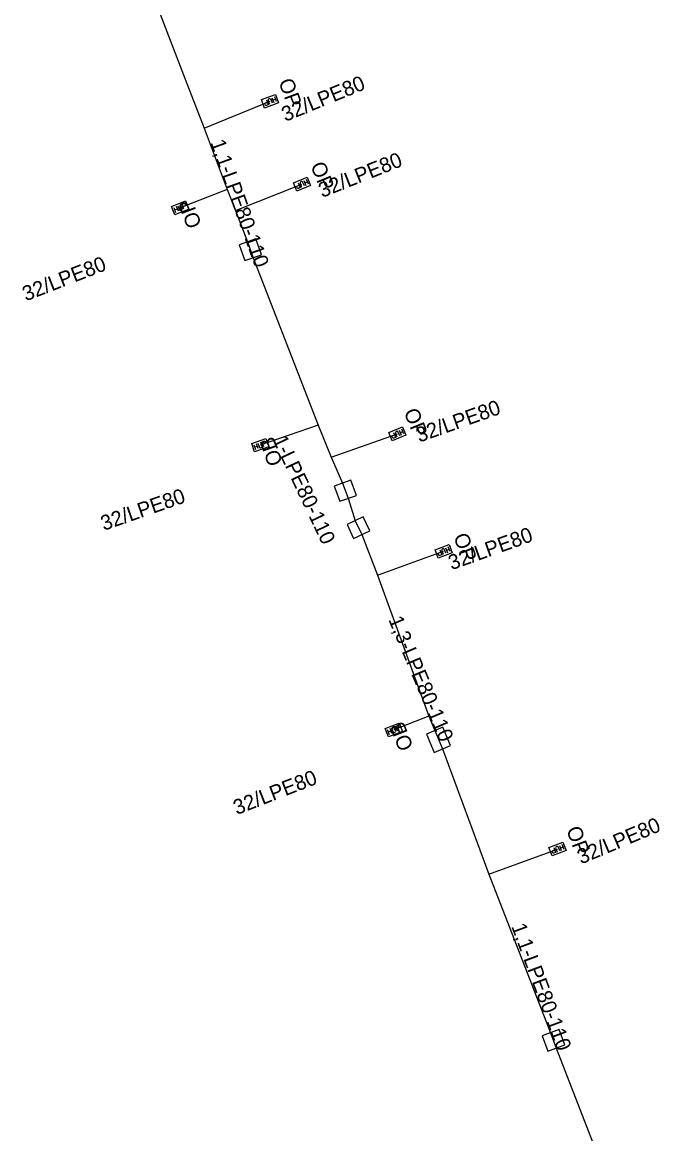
# Model space of a CAD drawing. Extents: x -762509 to -761250, y -1153000 to -1152256.
# Drawn here: x -761501.9 to -761459.2, y -1152484.2 to -1152409.7 of the extents above; entities that cross this region are included whole.
import ezdxf

# ---------------------------------------------------------------- set-up
doc = ezdxf.new("R2010")
doc.units = 0
for name, color, linetype in [('Vrstva 21', 7, 'Continuous'), ('Vrstva 29', 7, 'Continuous'), ('Vrstva 31', 7, 'Continuous'), ('Vrstva 32', 7, 'Continuous')]:
    doc.layers.add(name, color=color, linetype=linetype)

msp = doc.modelspace()

# ---------------------------------------------------------------- linework, layer by layer
at = {"layer": 'Vrstva 21'}
msp.add_lwpolyline([(-761494.58, -1152404.14), (-761490.85, -1152413.85), (-761489.7, -1152416.84), (-761488.16, -1152420.95), (-761487.6, -1152422.35), (-761486.8, -1152424.45), (-761486.42, -1152425.51), (-761482.06, -1152436.72), (-761481.18, -1152438.87), (-761480.42, -1152440.61), (-761480.05, -1152441.63), (-761479.58, -1152443.13), (-761479.14, -1152444.06), (-761478.09, -1152446.77), (-761474.65, -1152456.23), (-761474.25, -1152457.19), (-761473.73, -1152458.42), (-761470.62, -1152466.8), (-761466.48, -1152477.43), (-761466.1, -1152478.45), (-761462.35, -1152488.13)], dxfattribs=at)
at = {"layer": 'Vrstva 29'}
for points in [[(-761487.36, -1152424.65), (-761486.98, -1152425.71), (-761485.86, -1152425.31), (-761486.24, -1152424.25)], [(-761480.98, -1152440.81), (-761480.61, -1152441.83), (-761479.49, -1152441.43), (-761479.86, -1152440.41)], [(-761480.12, -1152443.39), (-761479.68, -1152444.32), (-761478.6, -1152443.8), (-761479.04, -1152442.87)], [(-761474.8, -1152457.42), (-761474.28, -1152458.65), (-761473.18, -1152458.19), (-761473.7, -1152456.96)], [(-761467.04, -1152477.64), (-761466.66, -1152478.66), (-761465.54, -1152478.24), (-761465.92, -1152477.22)]]:
    msp.add_lwpolyline(points, close=True, dxfattribs=at)
at = {"layer": 'Vrstva 31'}
for points in [[(-761489.7, -1152416.84), (-761489.69, -1152416.83), (-761485.28, -1152415.03)], [(-761488.16, -1152420.95), (-761491.3, -1152422.17)], [(-761487.6, -1152422.35), (-761483.14, -1152420.58)], [(-761482.06, -1152436.72), (-761485.94, -1152438.07)], [(-761481.18, -1152438.87), (-761476.75, -1152437.31)], [(-761478.09, -1152446.77), (-761473.65, -1152445.18)], [(-761474.65, -1152456.23), (-761476.99, -1152457.14)], [(-761470.62, -1152466.8), (-761466.02, -1152465.12)]]:
    msp.add_lwpolyline(points, dxfattribs=at)
at = {"layer": 'Vrstva 32'}
for p, q in [((-761485.529, -1152414.937), (-761485.406, -1152415.264)), ((-761485.155, -1152414.797), (-761485.032, -1152415.124)), ((-761484.902, -1152414.899), (-761485.09, -1152414.97)), ((-761484.844, -1152415.054), (-761484.967, -1152414.726)), ((-761483.022, -1152420.343), (-761482.89, -1152420.667)), ((-761482.704, -1152420.591), (-761482.836, -1152420.267)), ((-761483.392, -1152420.493), (-761483.26, -1152420.817)), ((-761482.766, -1152420.438), (-761482.952, -1152420.514)), ((-761491.736, -1152422.152), (-761491.609, -1152422.478)), ((-761491.676, -1152422.306), (-761491.489, -1152422.233)), ((-761491.422, -1152422.405), (-761491.549, -1152422.079)), ((-761491.05, -1152422.261), (-761491.177, -1152421.935)), ((-761477.002, -1152437.224), (-761476.869, -1152437.548)), ((-761476.633, -1152437.073), (-761476.5, -1152437.397)), ((-761476.376, -1152437.168), (-761476.562, -1152437.244)), ((-761476.314, -1152437.32), (-761476.447, -1152436.996)), ((-761486.375, -1152438.036), (-761486.26, -1152438.367)), ((-761486.321, -1152438.192), (-761486.131, -1152438.126)), ((-761486.07, -1152438.301), (-761486.185, -1152437.97)), ((-761485.694, -1152438.17), (-761485.809, -1152437.839)), ((-761473.214, -1152445.201), (-761473.339, -1152444.874)), ((-761473.9, -1152445.087), (-761473.775, -1152445.415)), ((-761473.527, -1152444.946), (-761473.402, -1152445.273)), ((-761473.273, -1152445.047), (-761473.461, -1152445.119)), ((-761477.426, -1152457.122), (-761477.299, -1152457.448)), ((-761477.366, -1152457.276), (-761477.179, -1152457.203)), ((-761477.112, -1152457.375), (-761477.239, -1152457.049)), ((-761476.74, -1152457.231), (-761476.867, -1152456.905)), ((-761466.269, -1152465.027), (-761466.146, -1152465.354)), ((-761465.895, -1152464.887), (-761465.773, -1152465.214)), ((-761465.642, -1152464.989), (-761465.83, -1152465.06)), ((-761465.584, -1152465.144), (-761465.707, -1152464.816))]:
    msp.add_line(p, q, dxfattribs=at)
for points in [[(-761484.707, -1152415.136), (-761485.643, -1152415.487), (-761485.854, -1152414.925), (-761484.917, -1152414.574), (-761484.707, -1152415.136)], [(-761485.406, -1152415.264), (-761485.528, -1152415.31), (-761485.573, -1152415.309), (-761485.593, -1152415.299), (-761485.617, -1152415.273), (-761485.635, -1152415.226), (-761485.633, -1152415.19), (-761485.625, -1152415.17), (-761485.592, -1152415.14), (-761485.47, -1152415.094)], [(-761485.125, -1152415.159), (-761485.213, -1152414.924), (-761485.244, -1152414.883), (-761485.284, -1152414.863), (-761485.329, -1152414.862), (-761485.357, -1152414.872), (-761485.39, -1152414.903), (-761485.405, -1152414.944), (-761485.401, -1152414.995), (-761485.313, -1152415.23)], [(-761482.564, -1152420.669), (-761483.49, -1152421.046), (-761483.717, -1152420.491), (-761482.791, -1152420.113), (-761482.564, -1152420.669)], [(-761483.26, -1152420.817), (-761483.38, -1152420.866), (-761483.425, -1152420.867), (-761483.445, -1152420.857), (-761483.471, -1152420.832), (-761483.49, -1152420.786), (-761483.489, -1152420.75), (-761483.481, -1152420.73), (-761483.449, -1152420.698), (-761483.328, -1152420.649)], [(-761482.982, -1152420.704), (-761483.077, -1152420.472), (-761483.108, -1152420.432), (-761483.149, -1152420.413), (-761483.195, -1152420.413), (-761483.221, -1152420.424), (-761483.254, -1152420.455), (-761483.268, -1152420.497), (-761483.263, -1152420.548), (-761483.168, -1152420.78)], [(-761491.875, -1152422.072), (-761490.942, -1152421.709), (-761490.725, -1152422.269), (-761491.657, -1152422.631), (-761491.875, -1152422.072)], [(-761491.456, -1152422.043), (-761491.366, -1152422.277), (-761491.335, -1152422.318), (-761491.294, -1152422.337), (-761491.249, -1152422.338), (-761491.222, -1152422.327), (-761491.189, -1152422.296), (-761491.173, -1152422.255), (-761491.178, -1152422.204), (-761491.269, -1152421.97)], [(-761491.177, -1152421.935), (-761491.056, -1152421.888), (-761491.01, -1152421.888), (-761490.991, -1152421.898), (-761490.966, -1152421.923), (-761490.947, -1152421.97), (-761490.949, -1152422.006), (-761490.957, -1152422.026), (-761490.99, -1152422.057), (-761491.111, -1152422.104)], [(-761476.174, -1152437.398), (-761477.099, -1152437.777), (-761477.327, -1152437.222), (-761476.402, -1152436.843), (-761476.174, -1152437.398)], [(-761476.869, -1152437.548), (-761476.989, -1152437.597), (-761477.035, -1152437.597), (-761477.055, -1152437.588), (-761477.08, -1152437.563), (-761477.099, -1152437.517), (-761477.099, -1152437.481), (-761477.091, -1152437.46), (-761477.058, -1152437.429), (-761476.938, -1152437.379)], [(-761476.591, -1152437.434), (-761476.687, -1152437.202), (-761476.718, -1152437.162), (-761476.759, -1152437.143), (-761476.805, -1152437.143), (-761476.832, -1152437.154), (-761476.864, -1152437.186), (-761476.878, -1152437.227), (-761476.873, -1152437.278), (-761476.777, -1152437.51)], [(-761486.511, -1152437.951), (-761485.566, -1152437.622), (-761485.369, -1152438.189), (-761486.314, -1152438.518), (-761486.511, -1152437.951)], [(-761486.092, -1152437.938), (-761486.009, -1152438.175), (-761485.98, -1152438.216), (-761485.94, -1152438.237), (-761485.895, -1152438.24), (-761485.867, -1152438.23), (-761485.833, -1152438.2), (-761485.817, -1152438.16), (-761485.82, -1152438.109), (-761485.902, -1152437.872)], [(-761485.809, -1152437.839), (-761485.686, -1152437.796), (-761485.641, -1152437.799), (-761485.621, -1152437.809), (-761485.597, -1152437.835), (-761485.581, -1152437.883), (-761485.583, -1152437.918), (-761485.592, -1152437.938), (-761485.626, -1152437.968), (-761485.749, -1152438.011)], [(-761473.076, -1152445.283), (-761474.011, -1152445.638), (-761474.224, -1152445.077), (-761473.29, -1152444.722), (-761473.076, -1152445.283)], [(-761473.775, -1152445.415), (-761473.897, -1152445.461), (-761473.942, -1152445.46), (-761473.962, -1152445.45), (-761473.986, -1152445.424), (-761474.004, -1152445.378), (-761474.003, -1152445.342), (-761473.995, -1152445.321), (-761473.961, -1152445.291), (-761473.84, -1152445.244)], [(-761473.495, -1152445.308), (-761473.584, -1152445.073), (-761473.614, -1152445.032), (-761473.655, -1152445.013), (-761473.7, -1152445.012), (-761473.728, -1152445.022), (-761473.761, -1152445.053), (-761473.776, -1152445.094), (-761473.772, -1152445.145), (-761473.683, -1152445.379)], [(-761477.565, -1152457.042), (-761476.633, -1152456.679), (-761476.415, -1152457.239), (-761477.347, -1152457.601), (-761477.565, -1152457.042)], [(-761477.147, -1152457.013), (-761477.056, -1152457.247), (-761477.025, -1152457.288), (-761476.984, -1152457.307), (-761476.939, -1152457.308), (-761476.912, -1152457.297), (-761476.879, -1152457.266), (-761476.864, -1152457.225), (-761476.868, -1152457.174), (-761476.959, -1152456.94)], [(-761476.867, -1152456.905), (-761476.746, -1152456.857), (-761476.701, -1152456.858), (-761476.681, -1152456.868), (-761476.656, -1152456.893), (-761476.638, -1152456.94), (-761476.639, -1152456.976), (-761476.647, -1152456.996), (-761476.68, -1152457.027), (-761476.801, -1152457.074)], [(-761465.447, -1152465.226), (-761466.383, -1152465.577), (-761466.594, -1152465.015), (-761465.657, -1152464.664), (-761465.447, -1152465.226)], [(-761465.865, -1152465.249), (-761465.953, -1152465.014), (-761465.984, -1152464.973), (-761466.024, -1152464.953), (-761466.07, -1152464.952), (-761466.097, -1152464.962), (-761466.13, -1152464.993), (-761466.146, -1152465.034), (-761466.142, -1152465.084), (-761466.054, -1152465.32)], [(-761466.146, -1152465.354), (-761466.268, -1152465.4), (-761466.313, -1152465.399), (-761466.333, -1152465.389), (-761466.358, -1152465.363), (-761466.375, -1152465.316), (-761466.374, -1152465.28), (-761466.365, -1152465.26), (-761466.332, -1152465.229), (-761466.21, -1152465.184)]]:
    msp.add_lwpolyline(points, dxfattribs=at)

# ---------------------------------------------------------------- texts
at = {"layer": 'Vrstva 29'}
for s, rotation, p in [('1,1-LPE80-110', 289.72228, (-761489.29, -1152417.79)), ('1-LPE80-110', 295.31969, (-761485.13, -1152437.69)), ('1,3-LPE80-110', 292.9169, (-761477.37, -1152449.75)), ('1,1-LPE80-110', 290.43283, (-761469.13, -1152470.3))]:
    msp.add_text(s, height=1, rotation=rotation, dxfattribs=at).set_placement(p)
at = {"layer": 'Vrstva 31'}
for rotation, p in [(22.20393, (-761484.26, -1152416.42)), (22.20393, (-761484.26, -1152416.42)), (21.6462, (-761481.79, -1152421.51)), (21.6462, (-761481.79, -1152421.51)), (21.23289, (-761501.64, -1152428.44)), (21.23289, (-761501.64, -1152428.44)), (19.39943, (-761475.29, -1152437.9)), (19.39943, (-761475.29, -1152437.9)), (19.18474, (-761496.42, -1152443.81)), (19.18474, (-761496.42, -1152443.81)), (19.70286, (-761473.12, -1152446.45)), (19.70286, (-761473.12, -1152446.45)), (21.25051, (-761487.51, -1152462.85)), (21.25051, (-761487.51, -1152462.85)), (22.79496, (-761464.44, -1152466.16)), (22.79496, (-761464.44, -1152466.16))]:
    msp.add_text('32/LPE80', height=1, rotation=rotation, dxfattribs=at).set_placement(p)
at = {"layer": 'Vrstva 32'}
for s, rotation, p in [('OP', 290.54972, (-761484.73, -1152413.72)), ('OP', 290.54972, (-761484.73, -1152413.72)), ('OP', 292.17869, (-761482.59, -1152419.33)), ('OP', 292.17869, (-761482.59, -1152419.33)), ('OP', 111.23289, (-761489.84, -1152423.3)), ('OP', 111.23289, (-761489.84, -1152423.3)), ('OP', 292.2876, (-761476.34, -1152435.84)), ('OP', 292.2876, (-761476.34, -1152435.84)), ('OB', 109.18474, (-761484.42, -1152439.25)), ('OB', 109.18474, (-761484.42, -1152439.25)), ('OP', 290.82306, (-761473.01, -1152444.18)), ('OP', 290.82306, (-761473.01, -1152444.18)), ('OB', 111.25051, (-761475.66, -1152458.3)), ('OB', 111.25051, (-761475.66, -1152458.3)), ('OP', 290.53386, (-761465.45, -1152463.81)), ('OP', 290.53386, (-761465.45, -1152463.81))]:
    msp.add_text(s, height=1, rotation=rotation, dxfattribs=at).set_placement(p)

doc.saveas('drawing.dxf')
